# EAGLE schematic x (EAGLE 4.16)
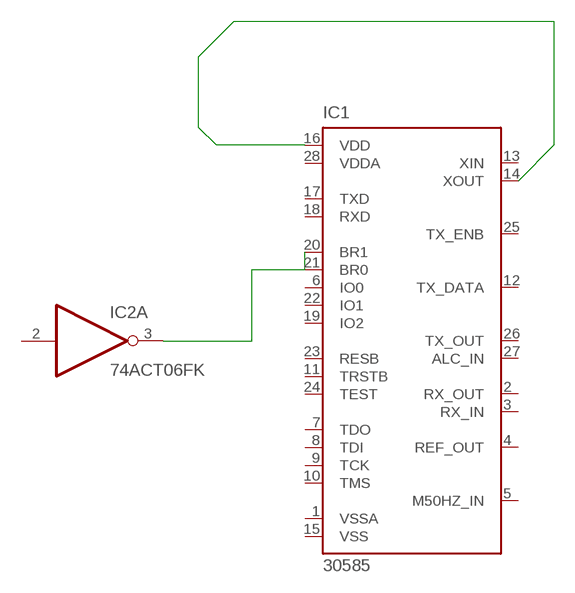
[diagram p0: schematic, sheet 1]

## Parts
IC1  30585  [PLCC28S]
IC2  74ACT06FK  [LCC20]

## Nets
N$1: IC1.20(BR1) IC2.3(A:O)
N$2: IC1.14(XOUT) IC1.16(VDD)
Unconnected: IC1.1(VSSA) IC1.2(RX_OUT) IC1.3(RX_IN) IC1.4(REF_OUT) IC1.5(M50HZ_IN) IC1.6(IO0) IC1.7(TDO) IC1.8(TDI) IC1.9(TCK) IC1.10(TMS) IC1.11(TRSTB) IC1.12(TX_DATA) IC1.13(XIN) IC1.15(VSS) IC1.17(TXD) IC1.18(RXD) IC1.19(IO2) IC1.21(BR0) IC1.22(IO1) IC1.23(RESB) IC1.24(TEST) IC1.25(TX_ENB) IC1.26(TX_OUT) IC1.27(ALC_IN) IC1.28(VDDA) IC2.2(A:I) IC2.4(B:I) IC2.6(B:O) IC2.8(C:I) IC2.9(C:O) IC2.12(D:O) IC2.13(D:I) IC2.14(E:O) IC2.16(E:I) IC2.18(F:O) IC2.19(F:I)

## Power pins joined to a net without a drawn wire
GND: IC2.10(P:GND)
VCC: IC2.20(P:VCC)

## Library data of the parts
IC1 = amis:30585: AMIS-30585 S-FSK PLC Modem Source: http://www.amis.com/pdf/amis_30585_ds.pdf
IC2 = 74xx-eu:74*06: Hex INVERTER, open collector high-voltage output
